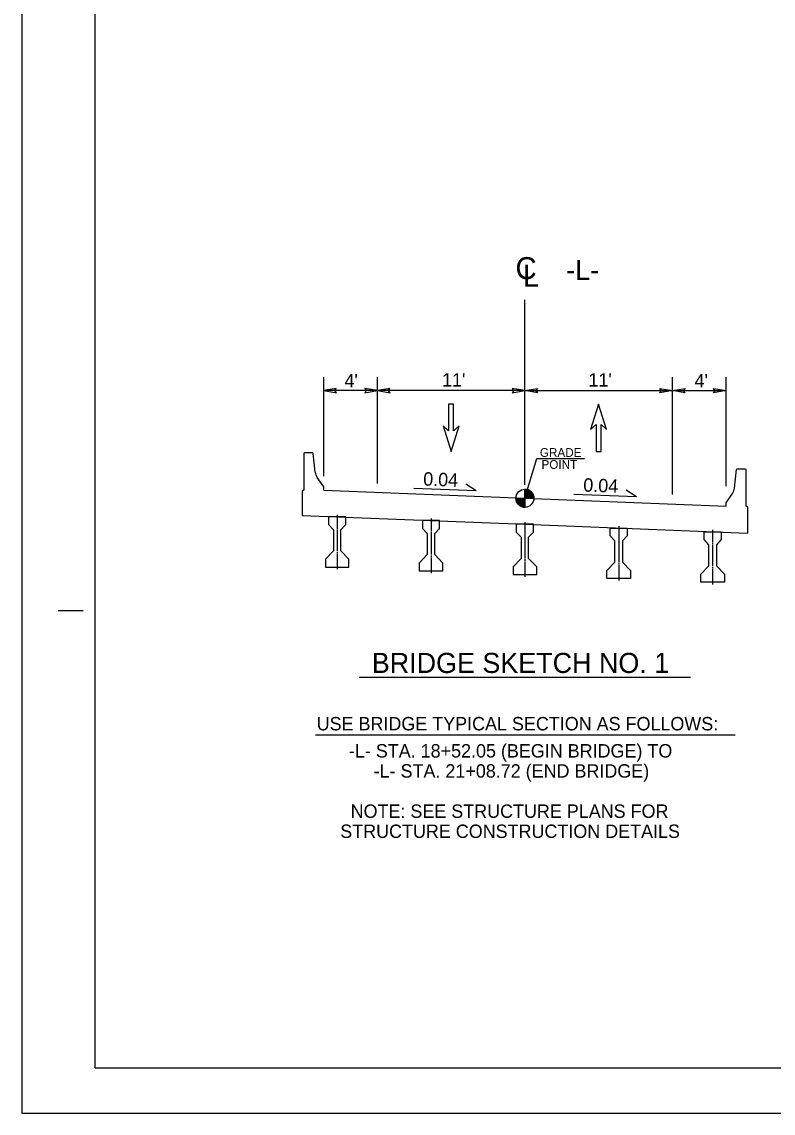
# Model space of a CAD drawing. Extents: x 1553884 to 1554215, y 810431 to 810779.
# Drawn here: x 1553901.4 to 1553957.4, y 810614.4 to 810695.8 of the extents above; entities that cross this region are included whole.
import ezdxf

# ---------------------------------------------------------------- set-up
doc = ezdxf.new("R2010")
doc.units = 0
for name, color, linetype in [('Old_Level_15', 7, 'Continuous'), ('Old_Level_2', 7, 'Continuous'), ('Prop Hatching', 7, 'Continuous'), ('Prop Lane Arrow CELL', 7, 'Continuous'), ('Scratch_Level_0', 7, 'Continuous'), ('Sheet Cutting Line CELL', 7, 'Continuous'), ('Sheet Data Field CELL', 7, 'Continuous'), ('Sheet Plot Border Outside CELL', 7, 'Continuous'), ('Sheet Sticker Exception Certification CELL', 7, 'Continuous'), ('Typical Arrow Superelevation CELL', 7, 'Continuous'), ('Typical Shoulder Slope CELL', 7, 'Continuous'), ('Typical Text Centerline CELL', 7, 'Continuous')]:
    doc.layers.add(name, color=color, linetype=linetype)

msp = doc.modelspace()

# ---------------------------------------------------------------- linework, layer by layer
at = {"layer": 'Old_Level_15'}
for points in [[(1553924.806, 810668.487), (1553923.868, 810668.326), (1553924.811, 810668.159), (1553924.691, 810668.326)], [(1553926.931, 810668.165), (1553927.868, 810668.326), (1553926.926, 810668.493), (1553927.045, 810668.326)], [(1553928.806, 810668.487), (1553927.868, 810668.326), (1553928.811, 810668.159), (1553928.691, 810668.326)], [(1553937.931, 810668.165), (1553938.868, 810668.326), (1553937.926, 810668.493), (1553938.045, 810668.326)], [(1553939.806, 810668.165), (1553938.868, 810668.326), (1553939.811, 810668.493), (1553939.691, 810668.326)], [(1553948.931, 810668.487), (1553949.868, 810668.326), (1553948.926, 810668.159), (1553949.045, 810668.326)], [(1553950.806, 810668.165), (1553949.868, 810668.326), (1553950.811, 810668.493), (1553950.691, 810668.326)], [(1553952.931, 810668.487), (1553953.868, 810668.326), (1553952.926, 810668.159), (1553953.045, 810668.326)]]:
    msp.add_lwpolyline(points, close=True, dxfattribs=at)
at = {"layer": 'Old_Level_2'}
for p, q in [((1553906.821, 810617.805), (1553906.825, 810776.052)), ((1553904.055, 810651.93), (1553905.93, 810651.928)), ((1553906.821, 810617.805), (1554154.321, 810617.805)), ((1553911.319, 810617.807), (1553911.319, 810617.807))]:
    msp.add_line(p, q, dxfattribs=at)
at = {"layer": 'Prop Hatching'}
for points in [[(1553933.962, 810665.701), (1553933.556, 810665.326), (1553933.556, 810667.326), (1553933.181, 810667.326), (1553933.181, 810665.326), (1553932.775, 810665.701), (1553933.368, 810663.795)], [(1553943.775, 810665.42), (1553944.181, 810665.795), (1553944.181, 810663.795), (1553944.556, 810663.795), (1553944.556, 810665.795), (1553944.962, 810665.42), (1553944.368, 810667.326)]]:
    msp.add_lwpolyline(points, close=True, dxfattribs=at)
at = {"layer": 'Prop Lane Arrow CELL'}
for p, q in [((1553901.353, 810779.427), (1553901.353, 810614.43)), ((1553901.353, 810614.43), (1554156.35, 810614.43))]:
    msp.add_line(p, q, dxfattribs=at)
at = {"layer": 'Scratch_Level_0'}
msp.add_line((1553901.353, 810614.43), (1553901.353, 810614.43), dxfattribs=at)
at = {"layer": 'Sheet Cutting Line CELL'}
for p, q in [((1553922.423, 810663.68), (1553922.391, 810663.648)), ((1553922.391, 810663.648), (1553922.391, 810660.899)), ((1553923.053, 810663.68), (1553922.423, 810663.68)), ((1553923.09, 810663.644), (1553923.053, 810663.68)), ((1553923.236, 810662.253), (1553923.09, 810663.644)), ((1553954.5, 810661.053), (1553954.646, 810662.444)), ((1553954.646, 810662.444), (1553954.683, 810662.48)), ((1553954.683, 810662.48), (1553955.313, 810662.48)), ((1553955.313, 810662.48), (1553955.346, 810662.448)), ((1553955.346, 810662.448), (1553955.346, 810659.699)), ((1553923.868, 810661.16), (1553923.389, 810661.845)), ((1553922.326, 810660.899), (1553922.26, 810660.834)), ((1553922.26, 810660.834), (1553922.26, 810660.378)), ((1553922.391, 810660.899), (1553922.326, 810660.899)), ((1553923.868, 810660.9), (1553923.868, 810661.16)), ((1553953.868, 810659.96), (1553954.348, 810660.645)), ((1553953.868, 810659.7), (1553953.868, 810659.96)), ((1553955.346, 810659.699), (1553955.411, 810659.699)), ((1553955.411, 810659.699), (1553955.476, 810659.634)), ((1553955.476, 810659.634), (1553955.476, 810659.178))]:
    msp.add_line(p, q, dxfattribs=at)
for centre, start, end in [((1553924.101, 810662.344), 186.01107, 214.9913), ((1553953.636, 810661.144), 325.0087, 353.98893)]:
    msp.add_arc(centre, 0.869, start, end, dxfattribs=at)
at = {"layer": 'Sheet Data Field CELL'}
for p, q in [((1553938.869, 810660.299), (1553938.869, 810660.971)), ((1553938.198, 810660.299), (1553938.869, 810660.299)), ((1553938.867, 810659.628), (1553938.869, 810660.299)), ((1553938.869, 810660.299), (1553938.867, 810659.628)), ((1553939.54, 810660.299), (1553938.869, 810660.299))]:
    msp.add_line(p, q, dxfattribs=at)
for points in [[(1553938.875, 810660.971), (1553938.875, 810660.971), (1553938.875, 810660.299)], [(1553938.888, 810660.971), (1553938.888, 810660.299)], [(1553938.902, 810660.969), (1553938.902, 810660.299)], [(1553938.915, 810660.969), (1553938.915, 810660.299)], [(1553938.929, 810660.968), (1553938.929, 810660.299)], [(1553938.942, 810660.966), (1553938.942, 810660.299)], [(1553938.955, 810660.965), (1553938.955, 810660.299)], [(1553938.969, 810660.963), (1553938.969, 810660.299)], [(1553938.982, 810660.962), (1553938.982, 810660.299)], [(1553938.996, 810660.959), (1553938.996, 810660.299)], [(1553939.009, 810660.956), (1553939.009, 810660.299)], [(1553939.023, 810660.953), (1553939.023, 810660.299)], [(1553939.036, 810660.95), (1553939.036, 810660.299)], [(1553939.049, 810660.945), (1553939.049, 810660.299)], [(1553939.063, 810660.942), (1553939.063, 810660.299)], [(1553939.076, 810660.938), (1553939.076, 810660.299)], [(1553939.09, 810660.934), (1553939.09, 810660.299)], [(1553939.103, 810660.929), (1553939.103, 810660.299)], [(1553939.117, 810660.923), (1553939.117, 810660.299)], [(1553939.13, 810660.917), (1553939.13, 810660.299)], [(1553939.143, 810660.911), (1553939.143, 810660.299)], [(1553939.157, 810660.905), (1553939.157, 810660.299)], [(1553939.17, 810660.899), (1553939.17, 810660.299)], [(1553939.184, 810660.892), (1553939.184, 810660.299)], [(1553939.197, 810660.884), (1553939.197, 810660.299)], [(1553939.211, 810660.877), (1553939.211, 810660.299)], [(1553939.224, 810660.869), (1553939.224, 810660.299)], [(1553939.237, 810660.86), (1553939.237, 810660.299)], [(1553939.251, 810660.851), (1553939.251, 810660.299)], [(1553939.264, 810660.841), (1553939.264, 810660.299)], [(1553939.278, 810660.832), (1553939.278, 810660.299)], [(1553939.291, 810660.822), (1553939.291, 810660.299)], [(1553939.305, 810660.81), (1553939.305, 810660.299)], [(1553938.201, 810660.299), (1553938.201, 810660.226)], [(1553938.214, 810660.299), (1553938.214, 810660.147)], [(1553938.227, 810660.299), (1553938.227, 810660.1)], [(1553938.241, 810660.299), (1553938.241, 810660.059)], [(1553938.254, 810660.299), (1553938.254, 810660.028)], [(1553938.268, 810660.299), (1553938.268, 810660)], [(1553938.281, 810660.299), (1553938.281, 810659.974)], [(1553938.295, 810660.299), (1553938.295, 810659.95)], [(1553938.308, 810660.299), (1553938.308, 810659.929)], [(1553938.321, 810660.299), (1553938.321, 810659.91)], [(1553938.335, 810660.299), (1553938.335, 810659.892)], [(1553938.348, 810660.299), (1553938.348, 810659.876)], [(1553938.362, 810660.299), (1553938.362, 810659.859)], [(1553938.375, 810660.299), (1553938.375, 810659.844)], [(1553938.389, 810660.299), (1553938.389, 810659.829)], [(1553938.402, 810660.299), (1553938.402, 810659.816)], [(1553938.415, 810660.299), (1553938.415, 810659.804)], [(1553938.429, 810660.299), (1553938.429, 810659.792)], [(1553938.442, 810660.299), (1553938.442, 810659.78)], [(1553938.456, 810660.299), (1553938.456, 810659.77)], [(1553938.469, 810660.299), (1553938.469, 810659.759)], [(1553938.482, 810660.299), (1553938.482, 810659.75)], [(1553938.496, 810660.299), (1553938.496, 810659.741)], [(1553938.509, 810660.299), (1553938.509, 810659.732)], [(1553938.523, 810660.299), (1553938.523, 810659.724)], [(1553938.536, 810660.299), (1553938.536, 810659.716)], [(1553938.55, 810660.299), (1553938.55, 810659.709)], [(1553938.563, 810660.299), (1553938.563, 810659.701)], [(1553938.577, 810660.299), (1553938.577, 810659.695)], [(1553938.59, 810660.299), (1553938.59, 810659.689)], [(1553938.603, 810660.299), (1553938.603, 810659.683)], [(1553938.617, 810660.299), (1553938.617, 810659.677)], [(1553938.63, 810660.299), (1553938.63, 810659.671)], [(1553938.644, 810660.299), (1553938.644, 810659.667)], [(1553938.657, 810660.299), (1553938.657, 810659.662)], [(1553938.67, 810660.299), (1553938.67, 810659.658)], [(1553938.684, 810660.299), (1553938.684, 810659.655)], [(1553938.697, 810660.299), (1553938.697, 810659.65)], [(1553938.711, 810660.299), (1553938.711, 810659.647)], [(1553938.724, 810660.299), (1553938.724, 810659.644)], [(1553938.738, 810660.299), (1553938.738, 810659.641)], [(1553938.751, 810660.299), (1553938.751, 810659.639)], [(1553938.764, 810660.299), (1553938.764, 810659.637)], [(1553938.778, 810660.299), (1553938.778, 810659.634)], [(1553938.791, 810660.299), (1553938.791, 810659.633)], [(1553938.805, 810660.299), (1553938.805, 810659.631)], [(1553938.818, 810660.299), (1553938.818, 810659.63)], [(1553938.832, 810660.299), (1553938.832, 810659.63)], [(1553938.845, 810660.299), (1553938.845, 810659.628)], [(1553938.859, 810660.299), (1553938.859, 810659.628), (1553938.859, 810659.628)], [(1553939.318, 810660.798), (1553939.318, 810660.299)], [(1553939.331, 810660.786), (1553939.331, 810660.299)], [(1553939.345, 810660.772), (1553939.345, 810660.299)], [(1553939.358, 810660.759), (1553939.358, 810660.299)], [(1553939.372, 810660.744), (1553939.372, 810660.299)], [(1553939.385, 810660.728), (1553939.385, 810660.299)], [(1553939.399, 810660.711), (1553939.399, 810660.299)], [(1553939.412, 810660.693), (1553939.412, 810660.299)], [(1553939.425, 810660.674), (1553939.425, 810660.299)], [(1553939.439, 810660.653), (1553939.439, 810660.299)], [(1553939.452, 810660.631), (1553939.452, 810660.299)], [(1553939.466, 810660.607), (1553939.466, 810660.299)], [(1553939.479, 810660.578), (1553939.479, 810660.299)], [(1553939.493, 810660.547), (1553939.493, 810660.299)], [(1553939.506, 810660.51), (1553939.506, 810660.299)], [(1553939.519, 810660.464), (1553939.519, 810660.299)], [(1553939.533, 810660.395), (1553939.533, 810660.299)]]:
    msp.add_lwpolyline(points, dxfattribs=at)
msp.add_circle((1553938.868, 810660.3), 0.671, dxfattribs=at)
for start, end in [(359.99048, 89.99048), (179.99048, 269.99048)]:
    msp.add_arc((1553938.868, 810660.3), 0.671, start, end, dxfattribs=at)
at = {"layer": 'Sheet Plot Border Outside CELL'}
for p, q in [((1553923.868, 810660.9), (1553938.868, 810660.3)), ((1553922.26, 810660.378), (1553922.26, 810659.017)), ((1553938.868, 810660.3), (1553953.868, 810659.7)), ((1553955.476, 810659.178), (1553955.476, 810657.688)), ((1553922.26, 810659.017), (1553938.868, 810658.353)), ((1553924.868, 810659.063), (1553924.868, 810658.112)), ((1553931.868, 810658.783), (1553931.868, 810657.832)), ((1553938.868, 810658.503), (1553938.868, 810657.552)), ((1553924.868, 810658.079), (1553924.868, 810657.96)), ((1553924.868, 810657.924), (1553924.868, 810656.37)), ((1553931.868, 810657.799), (1553931.868, 810657.68)), ((1553931.868, 810657.644), (1553931.868, 810656.09)), ((1553938.868, 810658.353), (1553955.476, 810657.688)), ((1553945.868, 810658.223), (1553945.868, 810657.272)), ((1553952.868, 810657.943), (1553952.868, 810656.992)), ((1553938.868, 810657.519), (1553938.868, 810657.4)), ((1553938.868, 810657.364), (1553938.868, 810655.81)), ((1553945.868, 810657.239), (1553945.868, 810657.12)), ((1553945.868, 810657.084), (1553945.868, 810655.53)), ((1553952.868, 810656.959), (1553952.868, 810656.84)), ((1553952.868, 810656.804), (1553952.868, 810655.25)), ((1553924.868, 810656.313), (1553924.868, 810656.188)), ((1553924.868, 810656.134), (1553924.868, 810654.996)), ((1553931.868, 810656.033), (1553931.868, 810655.908)), ((1553931.868, 810655.854), (1553931.868, 810654.716)), ((1553938.868, 810655.753), (1553938.868, 810655.628)), ((1553938.868, 810655.574), (1553938.868, 810654.436)), ((1553945.868, 810655.473), (1553945.868, 810655.348)), ((1553945.868, 810655.294), (1553945.868, 810654.156)), ((1553952.868, 810655.193), (1553952.868, 810655.068)), ((1553952.868, 810655.014), (1553952.868, 810653.876))]:
    msp.add_line(p, q, dxfattribs=at)
for points in [[(1553925.508, 810658.913), (1553924.868, 810658.913), (1553924.228, 810658.913), (1553924.228, 810658.329), (1553924.588, 810657.954), (1553924.588, 810656.371), (1553923.988, 810655.746), (1553923.988, 810655.163), (1553924.868, 810655.163), (1553925.748, 810655.163), (1553925.748, 810655.746), (1553925.148, 810656.371), (1553925.148, 810657.954), (1553925.508, 810658.329), (1553925.508, 810658.913)], [(1553932.508, 810658.633), (1553931.868, 810658.633), (1553931.228, 810658.633), (1553931.228, 810658.049), (1553931.588, 810657.674), (1553931.588, 810656.091), (1553930.988, 810655.466), (1553930.988, 810654.883), (1553931.868, 810654.883), (1553932.748, 810654.883), (1553932.748, 810655.466), (1553932.148, 810656.091), (1553932.148, 810657.674), (1553932.508, 810658.049), (1553932.508, 810658.633)], [(1553939.508, 810658.353), (1553938.868, 810658.353), (1553938.228, 810658.353), (1553938.228, 810657.769), (1553938.588, 810657.394), (1553938.588, 810655.811), (1553937.988, 810655.186), (1553937.988, 810654.603), (1553938.868, 810654.603), (1553939.748, 810654.603), (1553939.748, 810655.186), (1553939.148, 810655.811), (1553939.148, 810657.394), (1553939.508, 810657.769), (1553939.508, 810658.353)], [(1553945.228, 810658.073), (1553945.868, 810658.073), (1553946.508, 810658.073), (1553946.508, 810657.489), (1553946.148, 810657.114), (1553946.148, 810655.531), (1553946.748, 810654.906), (1553946.748, 810654.323), (1553945.868, 810654.323), (1553944.988, 810654.323), (1553944.988, 810654.906), (1553945.588, 810655.531), (1553945.588, 810657.114), (1553945.228, 810657.489), (1553945.228, 810658.073)], [(1553952.228, 810657.793), (1553952.868, 810657.793), (1553953.508, 810657.793), (1553953.508, 810657.209), (1553953.148, 810656.834), (1553953.148, 810655.251), (1553953.748, 810654.626), (1553953.748, 810654.043), (1553952.868, 810654.043), (1553951.988, 810654.043), (1553951.988, 810654.626), (1553952.588, 810655.251), (1553952.588, 810656.834), (1553952.228, 810657.209), (1553952.228, 810657.793)]]:
    msp.add_lwpolyline(points, dxfattribs=at)
at = {"layer": 'Sheet Sticker Exception Certification CELL'}
msp.add_lwpolyline([(1553938.868, 810660.3), (1553939.772, 810663.253), (1553943.31, 810663.253)], dxfattribs=at)
at = {"layer": 'Typical Arrow Superelevation CELL'}
for p, q in [((1553935.247, 810660.85), (1553930.589, 810661.036)), ((1553935.247, 810660.85), (1553934.473, 810661.339)), ((1553947.185, 810660.4), (1553946.411, 810660.889)), ((1553947.185, 810660.4), (1553942.527, 810660.586)), ((1553926.507, 810646.957), (1553951.229, 810646.957)), ((1553923.252, 810642.662), (1553954.561, 810642.662))]:
    msp.add_line(p, q, dxfattribs=at)
at = {"layer": 'Typical Shoulder Slope CELL'}
for p, q in [((1553938.868, 810661.299), (1553938.868, 810675.109)), ((1553923.868, 810661.952), (1553923.868, 810669.326)), ((1553927.868, 810661.393), (1553927.868, 810669.326)), ((1553949.868, 810660.58), (1553949.868, 810669.326)), ((1553953.868, 810661.21), (1553953.868, 810669.326)), ((1553927.868, 810668.326), (1553923.868, 810668.326)), ((1553938.868, 810668.326), (1553927.868, 810668.326)), ((1553938.868, 810668.326), (1553949.868, 810668.326)), ((1553949.868, 810668.326), (1553953.868, 810668.326))]:
    msp.add_line(p, q, dxfattribs=at)

# ---------------------------------------------------------------- texts
at = {"layer": 'Sheet Sticker Exception Certification CELL'}
for s, p in [('GRADE', (1553939.987, 810663.383)), ('POINT', (1553940.108, 810662.491))]:
    msp.add_text(s, height=0.6525, dxfattribs=at).set_placement(p)
at = {"layer": 'Typical Arrow Superelevation CELL'}
for s, height, p in [('-L-', 1.5, (1553941.956, 810676.58)), ("4'", 1, (1553925.414, 810668.567)), ("11'", 1, (1553932.694, 810668.626)), ("11'", 1, (1553943.609, 810668.626)), ("4'", 1, (1553951.52, 810668.567)), ('BRIDGE SKETCH NO. 1', 1.5, (1553927.453, 810647.265)), ('USE BRIDGE TYPICAL SECTION AS FOLLOWS:', 1, (1553923.342, 810642.982)), ('-L- STA. 18+52.05 (BEGIN BRIDGE) TO ', 1, (1553925.748, 810640.958)), ('-L- STA. 21+08.72 (END BRIDGE)', 1, (1553927.593, 810639.458)), ('NOTE: SEE STRUCTURE PLANS FOR', 1, (1553925.874, 810636.458)), ('STRUCTURE CONSTRUCTION DETAILS', 1, (1553925.1, 810634.958))]:
    msp.add_text(s, height=height, dxfattribs=at).set_placement(p)
for p in [(1553931.271, 810661.251), (1553943.209, 810660.801)]:
    msp.add_text('0.04', height=1, rotation=357.70939, dxfattribs=at).set_placement(p)
at = {"layer": 'Typical Text Centerline CELL'}
msp.add_text('C', height=1.64, dxfattribs=at).set_placement((1553938.166, 810676.643))
msp.add_text('L', height=1.641, rotation=359.9469, dxfattribs=at).set_placement((1553938.711, 810676.083))

doc.saveas('drawing.dxf')
